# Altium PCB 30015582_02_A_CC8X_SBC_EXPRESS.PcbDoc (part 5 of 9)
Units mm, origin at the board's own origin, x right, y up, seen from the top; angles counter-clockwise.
Board outline 87 x 63 mm, 6 copper layers (Top Layer-L1, GND Plane-L2, Signal-L3, PWR/Signal-L4, GND Plane-L5, Bottom Layer-L6), stack 1.172 mm thick; 169 components, 171 nets, 693 pads, 391 vias.
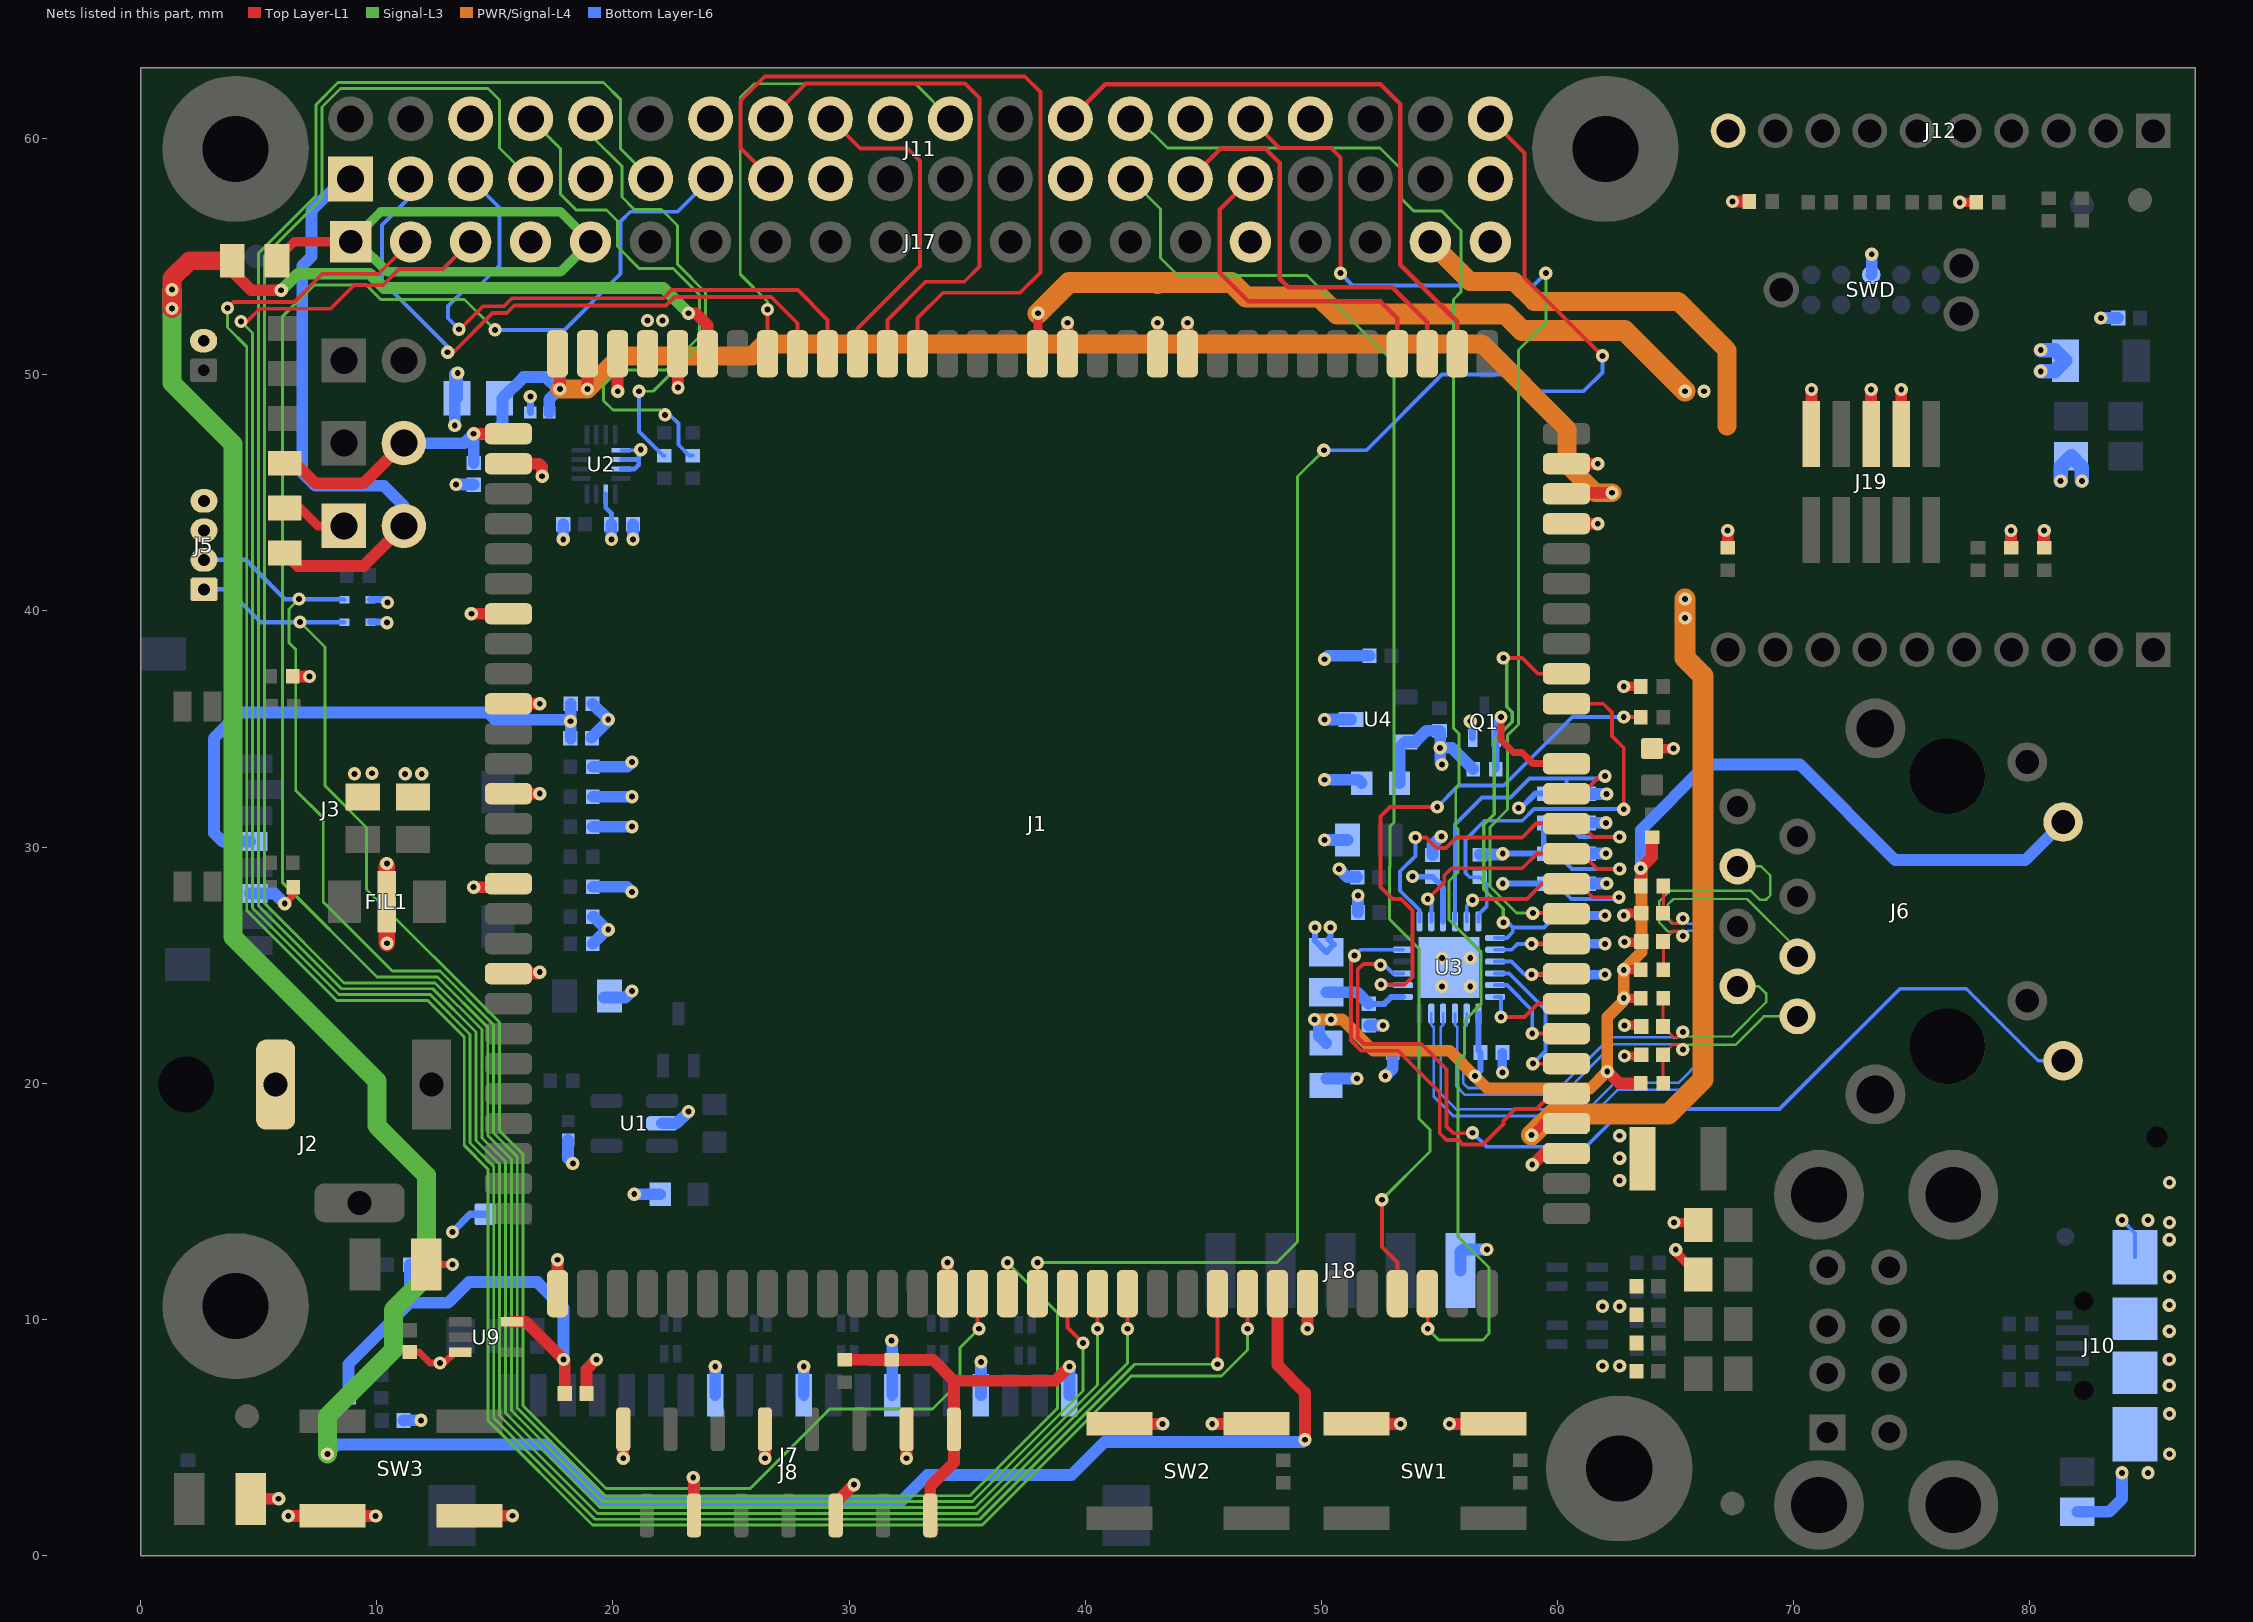
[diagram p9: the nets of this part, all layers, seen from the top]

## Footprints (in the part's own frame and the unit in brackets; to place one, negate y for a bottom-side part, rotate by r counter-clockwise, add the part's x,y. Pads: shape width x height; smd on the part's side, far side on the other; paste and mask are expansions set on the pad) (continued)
CC8X_CASTELLATED [mm] (continued)
  Top Layer-L1 keep-out region: 9.09,20.32 9.075,20.397 9.031,20.461 8.967,20.505 8.89,20.52 8.89,20.52 8.813,20.505 8.749,20.461 8.705,20.397 8.69,20.32 8.69,20.32 8.705,20.243 8.749,20.179 8.813,20.135 8.89,20.12 8.89,20.12 8.967,20.135 9.031,20.179 9.075,20.243 9.09,20.32
  Top Layer-L1 keep-out region: 10.36,20.32 10.345,20.397 10.301,20.461 10.237,20.505 10.16,20.52 10.16,20.52 10.083,20.505 10.019,20.461 9.975,20.397 9.96,20.32 9.96,20.32 9.975,20.243 10.019,20.179 10.083,20.135 10.16,20.12 10.16,20.12 10.237,20.135 10.301,20.179 10.345,20.243 10.36,20.32
  Top Layer-L1 keep-out region: 11.63,20.32 11.615,20.397 11.571,20.461 11.507,20.505 11.43,20.52 11.43,20.52 11.353,20.505 11.289,20.461 11.245,20.397 11.23,20.32 11.23,20.32 11.245,20.243 11.289,20.179 11.353,20.135 11.43,20.12 11.43,20.12 11.507,20.135 11.571,20.179 11.615,20.243 11.63,20.32
  Top Layer-L1 keep-out region: 12.9,20.32 12.885,20.397 12.841,20.461 12.777,20.505 12.7,20.52 12.7,20.52 12.623,20.505 12.559,20.461 12.515,20.397 12.5,20.32 12.5,20.32 12.515,20.243 12.559,20.179 12.623,20.135 12.7,20.12 12.7,20.12 12.777,20.135 12.841,20.179 12.885,20.243 12.9,20.32
  Top Layer-L1 keep-out region: 14.17,20.32 14.155,20.397 14.111,20.461 14.047,20.505 13.97,20.52 13.97,20.52 13.893,20.505 13.829,20.461 13.785,20.397 13.77,20.32 13.77,20.32 13.785,20.243 13.829,20.179 13.893,20.135 13.97,20.12 13.97,20.12 14.047,20.135 14.111,20.179 14.155,20.243 14.17,20.32
  Keep-Out Layer board cut-out: 16.78,9.93 16.742,10.121 16.634,10.284 16.471,10.392 16.28,10.43 16.28,10.43 -16.28,10.43 -16.471,10.392 -16.634,10.284 -16.742,10.121 -16.78,9.93 -16.78,9.93 -16.78,-9.93 -16.742,-10.121 -16.634,-10.284 -16.471,-10.392 -16.28,-10.43 -16.28,-10.43 16.28,-10.43 16.471,-10.392 16.634,-10.284 16.742,-10.121 16.78,-9.93 16.78,-9.93
  silkscreen extent -21.18,-22.6 20.1,22.6, body extent -20,-22.5 20,22.5, height 4.07
conn_CSCD443CCS011B00G [mil] "Bobbintron : CSCD443CCS011B00G"
  rect 65x150 hole 40 slot 126 at 90 deg: 1(0,0)
  rrect50% 65x150 / inner rect 65x150 / far side rrect50% 65x150 hole 40 slot 126 at 90 deg: 2(-260,0)
  rrect50% 150x65 / inner rect 150x65 / far side rrect50% 150x65 hole 40 slot 126 at 0 deg: 3(-120,-197.01)
  round 0 hole 93 unplated: 4(-409,0)
  silkscreen extent -570,-177 20,177, body extent -571,-207 20,177, height 433
FCI_68002-102HLF [mil]
  rect 74x74 hole 45: 1(0,0)
  round 74 hole 45: 2(100,0)
  silkscreen extent -50,-48 150,48, body extent -51,-46 149,49, height 330
FCI_SFW15S-2STE1LF [mm] "CONN FFC FPC VERT 15POS 1MM SMD"
  rrect50% 0.6x1.85 smd: 1(-7,-1.825) 2(-6,1.825) 3(-5,-1.825) 4(-4,1.825) 5(-3,-1.825) 6(-2,1.825) 7(-1,-1.825) 8(0,1.825) 9(1,-1.825) 10(2,1.825) 11(3,-1.825) 12(4,1.825) 13(5,-1.825) 14(6,1.825) 15(7,-1.825)
  silkscreen extent -10.9,-2.02 10.9,2.62, body extent -10.7,-2.25 10.7,2.25, height 5.31
fiducial_40mil_round [mil]
  round 40 smd paste-40 mask+20: 1(0,0)
  Top Layer-L1 pour cut-out: -40,0 -36.96,15.31 -28.28,28.28 -15.31,36.96 0,40 0,40 15.31,36.96 28.28,28.28 36.96,15.31 40,0 40,0 36.96,-15.31 28.28,-28.28 15.31,-36.96 0,-40 0,-40 -15.31,-36.96 -28.28,-28.28 -36.96,-15.31 -40,0
FIL_DLP11S [mm]
  rect 0.75x0.35 smd: 1(-0.65,-0.275) 2(0.65,-0.275) 3(0.65,0.275) 4(-0.65,0.275)
  body extent -0.67,-0.55 0.68,0.55, height 0.92
FIL_DLW21H [mm]
  rect 0.9x0.4 smd: 1(-0.85,-0.4) 2(0.85,-0.4) 3(0.85,0.4) 4(-0.85,0.4)
  body extent -1.1,-0.7 1.1,0.7, height 1
FIL_ELKEA [mm]
  rect 1.4x1.8 smd: 1(-1.8,0) 3(1.8,0)
  rect 0.8x2.6 smd: 2(0,0)
  body extent -1.6,-0.9 1.6,0.9, height 2.2
HIROSE_A2-20PA-2.54DSA(71) [mm]
  rect 1.75x1.75 hole 1 mask+0.1: 1(-24.13,0)
  round 1.75 hole 1 mask+0.1: 2(-21.59,0) 3(-19.05,0) 4(-16.51,0) 5(-13.97,0) 6(-11.43,0) 7(-8.89,0) 8(-6.35,0) 9(-3.81,0) 10(-1.27,0) 11(1.27,0) 12(3.81,0) 13(6.35,0) 14(8.89,0) 15(11.43,0) 16(13.97,0) 17(16.51,0) 18(19.05,0) 19(21.59,0) 20(24.13,0)
  silkscreen extent -25.33,-2.6 25.32,1.35, body extent -25.25,-1.27 25.25,1.27, height 8.55
HIROSE_DF14A-20P-1.25H [mm]
  rect 0.7x1.8 smd: 1(11.875,-2.55) 2(10.625,-2.55) 3(9.375,-2.55) 4(8.125,-2.55) 5(6.875,-2.55) 6(5.625,-2.55) 7(4.375,-2.55) 8(3.125,-2.55) 9(1.875,-2.55) 10(0.625,-2.55) 11(-0.625,-2.55) 12(-1.875,-2.55) 13(-3.125,-2.55) 14(-4.375,-2.55) 15(-5.625,-2.55) 16(-6.875,-2.55) 17(-8.125,-2.55) 18(-9.375,-2.55) 19(-10.625,-2.55) 20(-11.875,-2.55)
  rect 2x2.6 smd: MT1(14.275,2.55) MT21(-14.275,2.55)
  silkscreen extent -15,-3.05 15,3.7, body extent -14.97,-3.02 14.98,3.68, height 2.49
INDC2013X110N [mm]
  rect 1.2x1.45 smd: 1(-0.85,0) 2(0.85,0)
  body extent -1.1,-0.72 1.1,0.72, height 1.1
KYCON_KMMX-ABSMT5 [mm]
  rect 0.4x0.7 smd mask+0.058: 1(-1.3,3)
  rect 0.4x1.4 smd: 2(-0.65,2.65) 3(0,2.65) 4(0.65,2.65)
  rect 0.4x0.65 smd mask+0.058: 5(1.3,3.025)
  rect 2.3x1.9 smd: 6(-3.75,0) 9(3.75,0)
  rect 1.8x1.9 smd: 7(-1.15,0) 8(1.15,0)
  round 0 hole 0.813 unplated: 10(-1.9,2.18) 11(1.9,2.18)
  Top Layer-L1 region: 1.1,2.7 1.1,1.95 1.275,1.95 1.275,2.18 1.278,2.235 1.28,2.258 1.282,2.278 1.285,2.29 1.288,2.305 1.29,2.315 1.292,2.328 1.3,2.355 1.308,2.378 1.315,2.4 1.32,2.412 1.335,2.448 1.34,2.458 1.342,2.462 1.345,2.468 1.358,2.49 1.372,2.515 1.388,2.538 1.4,2.555 1.418,2.578 1.435,2.598 1.482,2.645 1.5,2.66 1.5,2.7
  Top Layer-L1 region: -1.1,2.7 -1.1,1.95 -1.275,1.95 -1.275,2.18 -1.278,2.235 -1.28,2.258 -1.282,2.278 -1.285,2.29 -1.288,2.305 -1.29,2.315 -1.292,2.328 -1.3,2.355 -1.308,2.378 -1.315,2.4 -1.32,2.412 -1.335,2.448 -1.34,2.458 -1.342,2.462 -1.345,2.468 -1.358,2.49 -1.372,2.515 -1.388,2.538 -1.4,2.555 -1.418,2.578 -1.435,2.598 -1.482,2.645 -1.5,2.66 -1.5,2.7
  silkscreen extent -3.75,-2.15 3.75,2.85, body extent -4.4,-2.72 4.4,2.88, height 2.78
KYCON_KUSBX-AS2N [mm]
  rect 1.524x1.524 hole 0.9: A1(0,0)
  round 1.524 hole 0.9: A2(2.5,0) A3(4.5,0) A4(7,0) B1(0,-2.62) B2(2.5,-2.62) B3(4.5,-2.62) B4(7,-2.62)
  round 3.81 hole 2.362: SH1(-3.07,-5.33) SH2(-3.07,0.35) SH3(10.07,-5.33) SH4(10.07,0.35)
  silkscreen extent -3.75,-15.58 10.75,1.42, body extent -4.33,-16.08 11.33,1.42, height 16.1
LEDM3020X130N [mm]
  rect 1.3x2.2 smd: A(-1.3,0) K(1.3,0)
  silkscreen extent -0.45,-1.1 2.25,1.1, body extent -1.6,-1.1 1.6,1.1, height 1.5
MOLEX_53047-0210 [mm]
  rrect20% 1x1.15 hole 0.5: 1(0,0)
  oval 1x1.15 hole 0.5: 2(1.25,0)
  silkscreen extent -2.51,-1.3 2.9,2.2, body extent -1.52,-1.15 2.73,2.05, height 4.2
MOLEX_53047-0410 [mm]
  rrect20% 1x1.15 hole 0.5: 1(0,0)
  oval 1x1.15 hole 0.5: 2(1.25,0) 3(2.5,0) 4(3.75,0)
  silkscreen extent -2.63,-1.33 5.43,2.22, body extent -1.52,-1.15 5.23,2.05, height 4.2
MOLEX_500873-0806 [mm]
  rect 0.8x1.5 smd: 1(0,0) 2(1.1,-0.4) 3(2.2,0) 4(3.3,0.2) 5(4.4,0) 6(5.5,0.2) 7(6.6,0) 8(7.7,0)
  rect 1.8x1.4 smd: 9(1.2,-10.3) 10(6.9,-10.3)
  rect 1.4x1.9 smd: 11(8.5,2.85) 12(-4.65,3.85)
  Top Layer-L1 keep-out region: 8.6,1.75 9.2,1.75 9.2,-11 8.6,-11
  silkscreen extent -5.05,-10.7 8.95,4.5, body extent -5.05,-10.7 8.95,4.5, height 1.87
PCBNUMBER [mm]
QFN40P260X180X55-16N [mm] "Quad Flat No-Lead (QFN), 0.40 mm pitch; rect., 4 pin X 4 pin, 2.60 mm L X 1.80 mm W X 0.55 mm H body"
  rect 0.81x0.2 smd: 1(-0.85,0.6) 2(-0.85,0.2) 3(-0.85,-0.2) 4(-0.85,-0.6) 9(0.85,-0.6) 10(0.85,-0.2) 11(0.85,0.2) 12(0.85,0.6)
  rect 0.2x0.81 smd: 5(-0.6,-1.25) 6(-0.2,-1.25) 7(0.2,-1.25) 8(0.6,-1.25) 13(0.6,1.25) 14(0.2,1.25) 15(-0.2,1.25) 16(-0.6,1.25)
  body extent -0.95,-1.35 0.95,1.35, height 0.55
QFN50P400X400X100-25T260X260N [mm] "Quad Flat No-Lead (QFN with Tab), 0.50 mm pitch; square, 6 pin X 6 pin, 4.00 mm L X 4.00 mm W X 1.00 mm H body"
  rrect54% 0.84x0.26 smd mask+0.05: 1(-1.95,1.25) 2(-1.95,0.75) 3(-1.95,0.25) 4(-1.95,-0.25) 5(-1.95,-0.75) 6(-1.95,-1.25) 13(1.95,-1.25) 14(1.95,-0.75) 15(1.95,-0.25) 16(1.95,0.25) 17(1.95,0.75) 18(1.95,1.25)
  rrect54% 0.26x0.84 smd mask+0.05: 7(-1.25,-1.95) 8(-0.75,-1.95) 9(-0.25,-1.95) 10(0.25,-1.95) 11(0.75,-1.95) 12(1.25,-1.95) 19(1.25,1.95) 20(0.75,1.95) 21(0.25,1.95) 22(-0.25,1.95) 23(-0.75,1.95) 24(-1.25,1.95)
  rect 2.6x2.6 smd paste-2.6 mask+0: 25(0,0)
  silkscreen extent -2.95,1.13 -2.75,1.32, body extent -2.05,-2.05 2.05,2.05, height 1
RESC1005X40N [mm]
  rect 0.57x0.62 smd mask+0.05: 1(-0.48,0) 2(0.48,0)
  body extent -0.5,-0.25 0.5,0.25, height 0.4
RESC1609X55N [mm]
  rect 0.9x1 smd mask+0.05: 1(-0.8,0) 2(0.8,0)
  body extent -0.87,-0.48 0.87,0.48, height 0.55
RESC2013X70N [mm]
  rect 1.05x1.4 smd: 1(-0.95,0) 2(0.95,0)
  body extent -1.1,-0.67 1.1,0.68, height 0.7
RESC3225X60N [mm]
  rect 1.1x2.7 smd: 1(-1.5,0) 2(1.5,0)
  body extent -1.7,-1.35 1.7,1.35, height 0.6
SAMTEC_FTSH-105-01-F-DV [mil]
  rect 110x29 smd: 1(-80,100) 2(80,100) 3(-80,50) 4(80,50) 5(-80,0) 6(80,0) 7(-80,-50) 8(80,-50) 9(-80,-100) 10(80,-100)
  silkscreen extent -172,93 -158,107, body extent -115,-208 115,208, height 325
SAMTEC_SQT-110-01-F-S [mm]
  rect 1.47x1.47 hole 0.98 paste-1.47: 1(0,0)
  round 1.47 hole 0.98 paste-1.47: 2(2,0) 3(4,0) 4(6,0) 5(8,0) 6(10,0) 7(12,0) 8(14,0) 9(16,0) 10(18,0)
  silkscreen extent -1.28,-1.12 19.28,1.12, body extent -1.15,-1 19.15,1, height 6.47
SODFL1006X43AN12 [mm]
  rect 0.43x0.32 smd: 1(-0.55,0) 2(0.55,0)
  body extent -0.58,-0.33 0.58,0.33, height 0.4
SOT65P210X100-3AN [mm]
  rect 0.5x1 smd: 1(-0.65,-1.1) 2(0.65,-1.1) 3(0,1.1)
  body extent -1.2,-1.12 1.2,1.12, height 1
SOT65P210X110-5N [mm]
  rect 0.4x0.95 smd: 1(-0.65,-1.1) 2(0,-1.1) 3(0.65,-1.1) 4(0.65,1.1) 5(-0.65,1.1)
  silkscreen extent -1.4,-1.1 1.1,0.67, body extent -1,-1.1 1,1.1, height 0.93
SOT95P240X110_GSD-3N [mm]
  rect 0.65x1.05 smd: D(0,1.15) G(-0.95,-1.15) S(0.95,-1.15)
  body extent -1.46,-1.2 1.46,1.2, height 1.1
SOT95P280X145-5N [mm]
  rrect50% 1.36x0.6 smd: 1(-1.18,0.95) 2(-1.18,0) 3(-1.18,-0.95) 4(1.18,-0.95) 5(1.18,0.95)
  body extent -1.4,-1.45 1.4,1.45, height 1.45
SOTFL50P160X80_GSD-3N [mm]
  rect 0.4x0.77 smd: D(0,0.69) G(-0.5,-0.69) S(0.5,-0.69)
  body extent -0.85,-0.85 0.85,0.85, height 0.8
SULLINS_GBC05SBSN-M89 [mil]
  rect 50x125 smd: 1(-200,-195) 2(-100,-195) 3(0,-195) 4(100,-195) 5(200,-195)
  silkscreen extent -258,-201 255,55, body extent -251,-233 249,277, height 140
SW_KSC221J [mm]
  rect 1x2.8 smd: 1(2,2.9) 2(2,-2.9) 3(-2,2.9) 4(-2,-2.9)
  silkscreen extent -3.1,-3.1 3.1,3.1, body extent -3.1,-3.4 3.1,3.4, height 3.5
SW_TDA02 [mm]
  rect 1.27x0.76 smd: 1(-3.81,0.635) 2(-3.81,-0.635) 3(3.81,-0.635) 4(3.81,0.635)
  silkscreen extent -4.25,-1.99 3.29,1.99, body extent -3.12,-1.84 3.13,1.84, height 2.3
TC_TC2050-IDC-NL [mil]
  round 31 smd paste-50: 1(-100,-25) 2(-50,-25) 3(0,-25) 4(50,-25) 5(100,-25) 6(100,25) 7(50,25) 8(0,25) 9(-50,25) 10(-100,25)
  round 59 hole 39.37 unplated: MT1(-150,0) MT2(150,40) MT3(150,-40)
  silkscreen extent -243,-91 243,91
TP0762 [mil] "30mil SMT Round Testpoint"
  round 30 smd paste-100: 1(0,0)
Wurth_61304021121 [mm] "CONN HEADER VERT 40POS 2.54"
  rect 1.9x1.9 hole 1.15: 1(0,0)
  round 1.9 hole 1.15: 2(0,2.54) 3(2.54,0) 4(2.54,2.54) 5(5.08,0) 6(5.08,2.54) 7(7.62,0) 8(7.62,2.54) 9(10.16,0) 10(10.16,2.54) 11(12.7,0) 12(12.7,2.54) 13(15.24,0) 14(15.24,2.54) 15(17.78,0) 16(17.78,2.54) 17(20.32,0) 18(20.32,2.54) 19(22.86,0) 20(22.86,2.54) 21(25.4,0) 22(25.4,2.54) 23(27.94,0) 24(27.94,2.54) 25(30.48,0) 26(30.48,2.54) 27(33.02,0) 28(33.02,2.54) 29(35.56,0) 30(35.56,2.54) 31(38.1,0) 32(38.1,2.54) 33(40.64,0) 34(40.64,2.54) 35(43.18,0) 36(43.18,2.54) 37(45.72,0) 38(45.72,2.54) 39(48.26,0) 40(48.26,2.54)
  silkscreen extent -2.14,-1.8 49.53,3.81, body extent -1.27,-1.27 49.53,3.81, height 8.57
XMultiple_XMG-9799-8821 [mm]
  round 1.524 hole 0.9: 1(1.27,6.35) 2(2.54,8.89) 3(3.81,6.35) 4(5.08,8.89) 5(6.35,6.35) 6(7.62,8.89) 7(8.89,6.35) 8(10.16,8.89)
  round 1.676 hole 1: 9(-0.61,-4.9) 10(1.93,-3.38) 11(9.5,-4.9) 12(12.04,-3.38)
  round 3.2 hole 3.2 unplated: MNT1(0,0) MNT2(11.43,0)
  round 2.54 hole 1.6: SHLD1(-2.035,3.05) SHLD2(13.465,3.05)
  silkscreen extent -2.29,-10.79 13.72,10.38, body extent -2.58,-10.96 14.02,10.38, height 13.57

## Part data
C1 C2 C29: library part 1000501, "CAP CER 47UF 6.3V 20% X5R 0805", Manufacturer="Taiyo Yuden", Manufacturer_Part_Number=JMK212BJ476MG-T, Package_Type=0805, Temp_Coef=X5R, Tolerance=20%, Voltage=6.3V
C3 C30: library part 1000073, "CAP CER 1UF 6.3V 20% X5R 0402", Manufacturer=Murata, Manufacturer_Part_Number=GRM155R60J105ME19D, Package_Type=0402, Temp_Coef=X5R, Voltage=6.3V
C4: library part 1001303, "CAP CER 2.2UF 16V 10% X5R 0603", Manufacturer="TDK Corporation", Manufacturer_Part_Number=C1608X5R1C225K080AB, Package_Type=0603, Tolerance=10%, Voltage=16V
C5 C22 C24: library part 1001168, "CAP CER 10UF 10V 20% X5R 0402", Manufacturer=Samsung, Manufacturer_Part_Number=CL05A106MP5NUNC, Package_Type=0402, Temp_Coef=X5R, Tolerance=20%, Voltage=10V
C6 C7 C8 C9 C10 C11 C13 C14 C15 C16 C21 C23 C25 C27 C28 C31 C33: library part 1000006, "CAP 100nF 16V 10% X7R 0402", Manufacturer=Murata, Manufacturer_Part_Number=GRM155R71C104KA88D, Package_Type=0402, Tolerance=10
C12 C17: library part 1000500, "CAP CER 4.7UF 25V 10% X5R 0805", Manufacturer=Murata, Manufacturer_Part_Number=GRM21BR61E475KA12L, Package_Type=0805, Temp_Coef=X5R, Tolerance=10%, Voltage=25V
C18: library part 1001167, "CAP CER 1UF 10V 10% X5R 0402", Manufacturer=Murata, Manufacturer_Part_Number=GRM155R61A105KE15D, Package_Type=0402, Temp_Coef=X5R, Tolerance=10%, Voltage=10V
C19: library part 1001576, "CAP CER 470PF 50V 5% NP0 0402", Manufacturer=Murata, Manufacturer_Part_Number=GRM1555C1H471JA01J, Package_Type=0402, Tolerance="+/- 5%"
C20: library part 1001024, "CAP CER 0.022UF 100V X7R 0603", Manufacturer="TDK Corporation", Manufacturer_Part_Number=C1608X7R2A223M080AA, Package_Type=0603
C26: library part 1000566, "CAP CER 100UF 10V 20% X5R 1206", Manufacturer="TDK Corporation", Manufacturer_Part_Number=C3216X5R1A107M, Package_Type=1206, Temp_Coef=X5R, Tolerance=20%, Voltage=10V
C32: library part 1000067, "CAP CER 1000PF 50V 10% X7R 0402", Manufacturer=Murata, Manufacturer_Part_Number=GRM155R71H102KA01D, Package_Type=0402
D1: library part 1000794, "DIODE SCHOTTKY 30V 200MA SOT323", Manufacturer="Fairchild Semiconductor", Manufacturer Alt 1=none, Manufacturer Part Num=0082610201, Package_Type=SOT323, Part Number=SDS1920004
D2 D3: library part 1001637, "TVS DIODE 3.3VWM SOD923", Manufacturer="On Semiconductor", Package_Type=SMT
D4: library part 1001190, "LED RED 653NM 20MA 1208 SMD", Manufacturer=Dialight, Package_Type=SMT
D5: library part 1001189, "LED GREEN 573NM 1208 SMD", Manufacturer=Dialight, Package_Type=SMT
FIDUCIAL1 FIDUCIAL2 FIDUCIAL3 FIDUCIAL7 FIDUCIAL8 FIDUCIAL9: library part CAD0023, "40 Mil Round Fiducial", Package_Type=SMT
FIL1: library part 1001918, "DNF 2 MHZ -1000 MHZ SMD", Manufacturer="Panasonic - ECG", Manufacturer_Part_Number=ELKEA333FA, Package_Type=SMT
J1: library part 1002609, "CC8X castellated - 55001984-02", Manufacturer=DIGI, Manufacturer_Part_Number=55001984-02, Package_Type=SMT
J2: library part 1001105, "DC Power Jack", Manufacturer="Bobbintron Electrical Corp", Package_Type=TH
J3: library part 1001118, "CONN TRANSFLSH R/A PUSH-PUSH SMD", Manufacturer=Molex, Package_Type=SMT
J4: library part 1001136, "CONN HEADER 2POS 1.25MM VERT TIN", Manufacturer=Molex, Manufacturer_Part_Number=53047-0210, Package_Type=TH
J5: library part 1001137, "CONN HEADER 4POS 1.25MM VERT TIN", Manufacturer=Molex, Manufacturer_Part_Number=53047-0410, Package_Type=TH
J6: library part 1001971, "CONN, RJ45 100BASE-T R/A, -40/85C", Manufacturer=XMultiple, Manufacturer_Part_Number=XMG-9799-8821-100D-L1TO-H-HIM, Package_Type=TH
J7: library part 1001132, "CONN HEADER 20POS 1.25MM R/A SMD", Manufacturer=Hirose, Manufacturer_Part_Number=DF14A-20P-1.25H, Package_Type=SMT
J8: library part 1001866, "CONN FFC FPC VERT 15POS 1MM SMD", Manufacturer=FCI, Package_Type=SMT
J9: library part 1001121, "USB Stacked Dual A type", Manufacturer=KYCON, Package_Type=TH
J10: library part 1001117, "CONN RECEPT MICRO-USB TYPE AB R/A", Manufacturer=KYCON, Package_Type=SMT
J11: library part 1002007, "CONN HEADER VERT 40POS 2.54", Manufacturer="Wurth Electronics Inc", Package_Type=TH
J12 J13: library part 1001648, "CONN RECEPT 10POS 10X1 2MM PCB TH", Manufacturer=Samtec, Package_Type=TH
J14 J15 J16: library part 1001128, "CONN HEADER 2POS .100\" SGL GOLD", Manufacturer=Samtec, Manufacturer_Part_Number=TSW-102-07-G-S, Package_Type=TH
J17: library part 1002537, "HEADER 20POS 2.54MM", Manufacturer=Hirose, Package_Type=TH
J18: library part 1002541, "CONN HEADER 5POS .100 RT/A SMD", Manufacturer=Sullins, Package_Type=SMT
J19: library part 1000034, "CONN HEADER 10POS DUAL .05\" SMD", Manufacturer=Samtec, Package_Type=SMT
L1 L7 L8 L9 L12 L13 L14 L15 L16: library part 1001174, "FERRITE BEAD 220 OHM 2.0A 0805", Manufacturer="Wurth Electronics Inc", Manufacturer_Part_Number=742792022, Package_Type=0805
L2 L3 L4 L5 L6: library part 1001014, "CHOKE COIL COMMON MODE 150MA SMD", Manufacturer=Murata, Manufacturer_Part_Number=DLP11SN900HL2L, Package_Type=SMT
L10 L11: library part 1001173, "CHOKE COM MODE 120 OHM .37A", Manufacturer="Wurth Electronics Inc", Package_Type=SMT
PCB1: library part 3000137, "PCB CCWM6_SBC_v0.3"
Q1: library part 1000715, "MOSFET N-CH 60V 115MA SOT-523F", Manufacturer="Fairchild Semiconductor", Package_Type=SOT523F
R1 R2 R8 R20 R77: library part 1001557, "RES 0.0 OHM 1/8W JUMP 0805 SMD", Manufacturer=Yageo, Manufacturer_Part_Number=RC0805JR-070RL, Package_Type=0805, Power=125
R3 R9 R23 R39 R44 R45 R46 R47 R48 R49 R50 R51 R52 R53 R55 R56 R58 R62 R63 R64 R65 R66 R67 R69 R76: library part 1000076, "RES 0.0 OHM 1/10W 0402 SMD", Manufacturer="Panasonic - ECG", Manufacturer_Part_Number=ERJ-2GE0R00X, Package_Type=0402, Power=10
R4 R5 R15 R16 R17 R18 R43 R54 R57 R60 R70 R72: library part 1000537, "RES 10.0K OHM 1/10W 1% 0402 SMD", Manufacturer="Panasonic - ECG", Manufacturer_Part_Number=ERJ-2RKF1002X, Package_Type=0402, Power=100, Tolerance=1%
R6: library part 1001200, "RES 12.0K OHM 1/10W 1% 0603 SMD", Manufacturer=Yageo, Manufacturer_Part_Number=RC0603FR-0712KL, Package_Type=0603, Power=100, Tolerance=1
R7: library part 1000142, "RES 20K OHM 1/10W 5% 0603 SMD", Manufacturer="Panasonic - ECG", Manufacturer_Part_Number=ERJ-3GEYJ203V, Package_Type=0603, Power=100, Tolerance=5
R10 R13 R24 R25 R26 R27 R28 R29 R30 R31 R32 R33: library part 1000038, "RES 4.7K OHM 1/10W 5% 0402 SMD", Manufacturer="Panasonic - ECG", Manufacturer_Part_Number=ERJ-2GEJ472X, Package_Type=0402, Power=100, Tolerance=5
R11 R12 R73: library part 1000480, "RES 100K OHM 1/10W 1% 0402 SMD", Manufacturer="Panasonic - ECG", Manufacturer_Part_Number=ERJ-2RKF1003X, Package_Type=0402, Power=100, Tolerance=1%
R14: library part 1001149, "RES 22.1K OHM 1/16W 1% 0402 SMD", Manufacturer="Vishay Dale", Manufacturer_Part_Number=CRCW040222K1FKED, Package_Type=0402, Power=0.063, Tolerance=±100ppm/°C
R19: library part 1000467, "RES 100 OHM 1/10W 1% 0402 SMD", Manufacturer="Panasonic - ECG", Manufacturer_Part_Number=ERJ-2RKF1000X, Package_Type=0402, Tolerance=1%
R22: library part 1000079, "RES 1.00K OHM 1/10W 1% 0402 SMD", Manufacturer="Panasonic - ECG", Manufacturer_Part_Number=ERJ-2RKF1001X, Package_Type=0402, Power=10
R34 R35 R36 R37: library part 1000466, "RES 49.9 OHM 1/10W 1% 0402 SMD", Manufacturer="Panasonic - ECG", Manufacturer_Part_Number=ERJ-2RKF49R9X, Package_Type=0402, Power=100, Tolerance=1%
R38: library part 1000828, "RES 12.1K OHM 1/10W 1% 0402 SMD", Manufacturer="Panasonic - ECG", Manufacturer_Part_Number=ERJ-2RKF1212X, Package_Type=0402, Power=100, Tolerance=1%
R40 R41: library part 1000465, "RES 150 OHM 1/10W 1% 0402 SMD", Manufacturer="Panasonic - ECG", Manufacturer_Part_Number=ERJ-2RKF1500X, Package_Type=0402, Power=100, Tolerance=1%
R42: library part 1000229, "RES 0.0 OHM 1/2W 1210 SMD", Manufacturer="Vishay Dale", Manufacturer_Part_Number=CRCW12100000Z0EA, Package_Type=1210
R59 R61 R68: library part 1001158, "RES 120 OHM 1/16W 1% 0402 SMD", Manufacturer=Yageo, Manufacturer_Part_Number=RC0402FR-07120RL, Package_Type=0402, Tolerance=1%
R71: library part 1000208, "RES 0.0 OHM 1/10W 0603", Manufacturer="Panasonic - ECG", Manufacturer_Part_Number=ERJ-3GEY0R00V, Package_Type=0603, Voltage=75V
R74 R75: library part 1001156, "RES 2.20K OHM 1/16W 1% 0402 SMD", Manufacturer=Yageo, Manufacturer_Part_Number=RC0402FR-072K2L, Package_Type=0402, Tolerance=1%
S3: library part 1001500, "SWITCH DIP 2POS HALF PITCH 24V", Manufacturer="C&K Components", Package_Type=SMT
SW1 SW2 SW3: library part 1001124, "SWITCH TACTILE SPST-NO 0.05A 32V", Manufacturer=ITT, Package_Type=SMT
SWD: library part CAD0066, "CBL PLUG-OF-NAILS 10-PIN", Package_Type=SMT
TP3: library part CAD0011, "TEST POINT 30mil PAD SMT", Package_Type=TP
U1: library part 1001979, "IC REG LDO ADJ 0.15A SOT25", Manufacturer="Diodes, Inc.", Manufacturer_Part_Number=AP2202K-ADJTRG1, Package_Type=SOT23-5
U2: library part 1002531, "IC BUS TRANSCVR TRI-ST DL 10UQFN", Manufacturer="Texas Instruments", Manufacturer_Part_Number=SN74AVC2T245RSWR, Package_Type=QFN
U3: library part 1001970, "TXRX ETHERNET 10/100 24VQFN", Manufacturer=Micrel, Manufacturer_Part_Number=LAN8720Ai-CP-TR, Package_Type=SMT
U4: library part 1001163, "MOSFET P-CH 20V 3.7A SOT23-3", Manufacturer="Vishay Siliconix", Package_Type=SMT
U9: library part 1000759, "TRANSLATOR 1BIT UNIDIRECT SC70-", Manufacturer="Fairchild Semiconductor", Package_Type=SC70

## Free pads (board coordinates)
  round 0.6 hole 0.9 unplated: 0(85.375,17.725)
  round 6.2 hole 2.8: TOOL1(4.02,59.563) TOOL2(62.02,59.563) TOOL3(4.02,10.563) TOOL4(62.611,3.683)

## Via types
v1: diameter 0.56, hole 0.25, Top Layer-L1 to Bottom Layer-L6, 391 vias

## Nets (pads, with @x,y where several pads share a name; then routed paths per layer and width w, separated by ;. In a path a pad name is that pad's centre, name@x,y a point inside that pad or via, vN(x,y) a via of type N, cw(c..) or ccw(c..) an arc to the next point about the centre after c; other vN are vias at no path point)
1V8: J1.27 J1.84 R77.2 | length 133.3
  Top Layer-L1 w0.5: R77.2@3.875,54.825 3.875,54.375 4.675,53.575 v1(5.95,53.575) ; v1(23.2,52.6) 23.5,52.6 24.003,52.097 J1.27@24.003,50.888 ; J1.84@48.133,11.088 48.133,8.067 49.3,6.9 v1(49.3,4.9)
  Top Layer-L1 w0.8: v1(1.325,52.8) v1(1.325,53.6) 1.325,54.075 2.075,54.825 R77.2@3.875,54.825
  Signal-L3 w0.5: v1(5.95,53.575) 6.65,54.275 9.7,54.275 10.3,53.675 22.125,53.675 v1(23.2,52.6)
  Signal-L3 w0.8: v1(1.325,53.6) v1(1.325,52.8) 1.325,49.65 3.902,47.073 3.902,26.198 10,20.1 10,18.2 12.1,16.1 12.1,11.8 10.7,10.4 10.7,8.7 7.904,5.904 v1(7.904,4.296)
  Bottom Layer-L6 w0.5: v1(7.904,4.296) 8.308,4.7 17.2,4.7 19.6,2.3 32.2,2.3 33.307,3.407 39.414,3.407 40.814,4.807 49.207,4.807 v1(49.3,4.9)
1V8_EXT: J17.1 J17.5 R77.1 | length 26.3
  Top Layer-L1 w0.4: R77.1@5.8,54.425 5.8,54.925 6.501,55.626 J17.1@8.89,55.626
  Signal-L3 w0.4: J17.1@8.89,55.626 9.174,55.626 10.449,54.351 17.775,54.351 J17.5@19.05,55.626 17.775,56.901 10.165,56.901 J17.1@8.89,55.626
3V3: J1.12 J1.16 J1.29 J1.95 J14.1 R1.2 | length 67
  Top Layer-L1 w0.381: R1.2@6.1,44.35 6.75,44.35 7.5,43.6 J14.1@8.6,43.6 J14.1@9.3,43.6 ; J1.16@37.973,50.888 38,50.915 v1(38,52.6) ; J1.12@43.053,50.888 v1(43.053,52.2) ; v1(58.9,17.8) 59.388,18.288 J1.95@60.373,18.288
  PWR/Signal-L4 w0.889: v1(38,52.6) 39.3,53.9 43.1,53.9 ; 43.053,53.853 43.1,53.9 ; v1(58.9,17.8) 59.8,18.7 64.7,18.7 66.151,20.151 66.151,37.249 65.4,38 v1(65.4,39.7) v1(65.4,40.5) ; v1(65.4,49.3) 62.825,51.875 58.5,51.875 57.8,52.575 50.65,52.575 49.925,53.3 46.8,53.3 46.2,53.9 43.1,53.9
  other v1: 66.2,49.3 21.463,52.3 22.1,52.3
3V3_ETH0: C9.1 C32.2 L1.1 R22.1 R23.2 R24.2 R25.2 R26.1 R27.1 R28.1 R29.1 R71.2 U3.9 U4.D | length 20.7
  Bottom Layer-L6 w0.25: v1(49.725,26.6) 49.725,26.025 L1.1@50.2,25.55 50.525,25.875 50.3,26.1 50.375,26.175 v1(50.375,26.6) ; v1(53.85,28.75) 53.86,28.74 C9.1@54.7,28.74 55.15,28.29 U3.9@55.15,26.85 ; v1(57.675,28.448) R27.1@59.413,28.448 ; v1(57.675,29.718) R28.1@59.413,29.718 R29.1@59.413,31.018 ; v1(58.35,31.65) 58.45,31.65 59.058,32.258 R26.1@59.413,32.258
  Bottom Layer-L6 w0.4: R24.2@60.88,24.6 v1(62,24.6) ; R25.2@60.88,25.9 v1(62,25.9) ; R23.2@60.88,27.1 v1(62,27.1)
  Bottom Layer-L6 w0.5: v1(50.125,32.85) 51.55,32.85 R71.2@51.7,32.7 ; v1(50.125,35.4) U4.D@51.25,35.4 ; v1(50.125,37.95) 50.275,38.1 C32.2@52.04,38.1 ; R22.1@56.7,29.68 57.637,29.68 v1(57.675,29.718)
3V3_EXT: C5.2 C6.2 C8.2 C21.2 J3.4 J5.3 J7.1 J8.1 J8.2 J11.1 J11.17 J14.2 J17.19 L15.1 R1.1 R14.2 R15.2 R16.2 R17.2 R18.2 R60.2 R68.1 R70.2 R71.1 R72.2 R73.2 R74.2 R75.2 U2.6 U4.S U9.5 | length 124.2
  Top Layer-L1 w0.5: R1.1@6.1,42.45 6.65,41.9 9.44,41.9 J14.2@11.14,43.6 ; U9.5@15.725,9.9 16.3,9.9 v1(17.9,8.3) 17.955,8.245 C21.2@17.955,6.858 ; R74.2@29.807,8.287 30.893,8.287 30.9,8.28 R75.2@31.8,8.28 33.551,8.28 34.433,7.397 ; J8.2@33.533,1.1 33.433,1 J8.2@33.433,1.694 33.433,2.933 34.433,3.933 J8.1@34.433,5.344 34.433,7.397 ; v1(39.328,8) 38.726,7.397 34.433,7.397
  PWR/Signal-L4 w0.8: J17.19@54.61,55.626 56.286,53.95 58.15,53.95 59,53.1 65.1,53.1 67.175,51.025 67.175,47.825
  Bottom Layer-L6 w0.2: U2.6@19.696,44.955 19.696,44.365 19.933,44.128 19.933,43.673 C8.2@19.925,43.665
  Bottom Layer-L6 w0.5: J3.4@4.626,30.228 3.472,30.228 3.1,30.6 3.1,34.6 4.2,35.7 14.7,35.7 15.009,35.391 v1@18.209,35.391 ; R60.2@8.8,6.68 8.8,8.1 11.4,10.7 ; J11.1@8.89,58.293 8.593,58.293 7.232,56.932 7.232,55.003 6.843,54.614 6.843,45.857 7.4,45.3 10.3,45.3 11.14,44.46 J14.2@11.14,43.6 ; R68.1@11.402,12.319 11.402,10.702 13.027,10.702 13.9,11.575 16.8,11.575 17.9,10.475 v1(17.9,8.3) ; v1(18.2,35.325) 18.2,35.382 v1@18.209,35.391 ; C5.2@18.209,34.6 v1@18.209,35.391 ; C6.2@18.209,36.068 v1@18.209,35.391 ; R70.2@19.149,25.908 19.741,26.5 19.19,27.051 R17.2@19.149,27.051 ; R18.2@19.149,28.321 20.579,28.321 v1(20.8,28.1) ; R14.2@19.149,30.861 v1(20.8,30.861) ; R15.2@19.149,32.131 v1(20.8,32.131) ; R16.2@19.149,33.401 20.601,33.401 v1(20.8,33.6) ; C8.2@19.925,43.665 19.925,43.036 v1(19.933,43.028) ; J7.1@39.328,6.794 v1(39.328,8) ; R71.1@53.3,32.7 53.3,34.2 U4.S@53.55,34.45 53.975,34.45 54.445,34.92 R72.2@55,34.92 55.025,34.895 v1(55.025,34.2) ; v1(55.1,33.5) 55.025,33.575 v1(55.025,34.2) ; R73.2@56.42,33.3 55.52,34.2 v1(55.025,34.2)
  Bottom Layer-L6 w0.61: v1(81.3,45.5) 81.3,46.1 L15.1@81.742,46.542 82.2,46.084 v1(82.2,45.5)
  other v1: 19.8,26.5
5V_CC8X: C29.2 C30.2 C31.1 J1.31 J1.32 J1.33 J1.116 J15.2 R2.2 | length 73.6
  Top Layer-L1 w0.5: R2.2@6.1,46.25 6.55,46.25 7.4,45.4 9.44,45.4 J15.2@11.14,47.1 ; v1(14.1,47.5) 15.571,47.5 J1.33@15.573,47.498 ; J1.32@17.653,50.888 17.75,50.791 v1(17.75,49.4) ; v1(18.923,49.4) J1.31@18.923,50.888 ; J1.116@60.373,44.958 60.415,45 v1(62.3,45)
  PWR/Signal-L4 w0.8: v1(17.75,49.4) v1(18.923,49.4) 20.323,50.8 25.9,50.8 26.4,51.3 56.8,51.3 60.4,47.7 60.4,46.2 61.6,45 v1(62.3,45)
  Bottom Layer-L6 w0.5: J15.2@11.14,47.1 13.7,47.1 v1(14.1,47.5) ; C31.1@14.1,46.26 v1(14.1,47.5) ; C30.2@17.3,48.4 17.3,48.95 v1(17.75,49.4) ; v1(18.923,49.4) v1(17.75,49.4) ; v1(14.1,47.5) 14.9,47.5 15.315,47.915 15.315,49 16.215,49.9 17.153,49.9 17.653,49.4 v1(17.75,49.4)
ADC_IN0: J1.83 J17.2 | length 102.3
  Top Layer-L1 w0.165: v1(3.675,52.825) 3.935,53.085 6.51,53.085 7.7,54.275 10.079,54.275 J17.2@11.43,55.626 ; v1(46.863,9.6) J1.83@46.863,11.088
  Signal-L3 w0.122: v1(3.675,52.825) 3.675,52 4.49,51.185 4.49,27.31 8.3,23.5 12.158,23.5 13.7,21.958 13.7,17.37 14.7,16.37 14.7,5.726 19.139,1.287 35.632,1.287 41.945,7.6 45.762,7.6 46.863,8.701 v1(46.863,9.6)
ADC_IN1: J1.82 J17.3 | length 102.4
  Top Layer-L1 w0.165: v1(4.25,52.25) 4.5,52.25 5.043,52.793 8.043,52.793 9.04,53.79 10.263,53.79 10.942,54.468 12.793,54.468 13.951,55.626 J17.3@13.97,55.626 ; J1.82@45.593,11.088 45.593,9.015 45.6,9.008 v1(45.6,8.1)
  Signal-L3 w0.122: v1(4.25,52.25) 4.739,51.761 4.739,27.413 8.403,23.749 12.261,23.749 13.949,22.061 13.949,17.473 14.949,16.473 14.949,5.829 19.242,1.536 35.529,1.536 42.093,8.1 v1(45.6,8.1)
AVDD1: C10.2 C11.1 C12.2 J6.11 L1.2 R34.2 R35.2 R36.2 R37.2 R39.1 U3.1 U3.19 | length 59
  Top Layer-L1 w0.4: v1(62.8,23.6) R35.2@63.52,23.6 ; v1(62.8,24.8) R37.2@63.52,24.8
  Top Layer-L1 w0.5: v1(62.1,20.5) 62.6,20 R34.2@63.52,20 ; R36.2@63.52,28.35 v1(63.52,29.1) 64,29.58 R39.1@64,30.42
  PWR/Signal-L4 w0.5: v1(49.7,22.7) v1(50.4,22.7) 50.875,22.7 52.2,21.375 55.425,21.375 v1(56.5,20.3) 57.025,19.775 61.375,19.775 v1(62.1,20.5) 62.1,22.8 62.8,23.5 v1(62.8,23.6) v1(62.8,24.8) 63.557,25.557 63.557,29.063 v1(63.52,29.1)
  Bottom Layer-L6 w0.25: C11.1@52,23.36 52.66,23.36 52.95,23.65 U3.1@53.45,23.65 ; v1(56.5,20.3) 56.74,20.54 C10.2@56.74,21.3 56.65,21.39 U3.19@56.65,22.95
  Bottom Layer-L6 w0.5: v1(49.7,22.7) 49.9,22.5 49.9,22 C12.2@50.2,21.7 ; L1.2@50.2,23.85 51.51,23.85 C11.1@52,23.36 ; v1(63.52,29.1) 63.52,30.72 66.3,33.5 70.25,33.5 74.3,29.45 79.794,29.45 J6.11@81.403,31.058
CONSOLE_RX: D2.2 J1.75 J5.2 | length 80.6
  Top Layer-L1 w0.165: v1(36.7,12.4) 36.703,12.397 J1.75@36.703,11.088
  Signal-L3 w0.121: 6.282,38.65 6.282,40.082 v1(6.7,40.5)
  Signal-L3 w0.122: 6.282,38.65 6.568,38.364 6.568,32.4 7.732,31.236 7.732,27.668 10.655,24.745 12.673,24.745 14.945,22.473 14.945,17.886 15.945,16.886 15.945,6.242 19.654,2.532 35.118,2.532 38.818,6.232 38.818,10.282 v1(36.7,12.4)
  Bottom Layer-L6 w0.191: J5.2@2.68,42.158 4.442,42.158 6.1,40.5 v1(6.7,40.5) 8.6,40.5 D2.2@8.625,40.475
CONSOLE_TX: D3.2 J1.74 J5.1 | length 69.5
  Top Layer-L1 w0.165: J1.74@35.433,11.088 35.433,9.667 v1(35.5,9.6)
  Signal-L3 w0.122: v1(6.75,39.525) 7.8,38.475 7.8,32.596 9.568,30.828 9.568,28.202 15.194,22.576 15.194,17.989 16.194,16.989 16.194,6.345 19.706,2.832 25.809,2.832 29.177,6.2 33.528,6.2 34.7,7.372 34.7,8.8 v1(35.5,9.6)
  Bottom Layer-L6 w0.191: J5.1@2.68,40.908 3.692,40.908 5.075,39.525 v1(6.75,39.525) D3.2@8.625,39.525
ENET0_CLK: J1.96 U3.5 | length 18.7
  Top Layer-L1 w0.165: v1(51.4,25.4) 51.241,25.241 51.241,21.807 51.674,21.375 53.245,21.375 55.008,19.612 55.008,17.879 55.301,17.586 55.8,17.586 55.976,17.41 56.836,17.41 57.7,18.274 57.7,18.4 58.2,18.9 59.1,18.9 59.758,19.558 J1.96@60.373,19.558
  Bottom Layer-L6 w0.165: v1(51.4,25.4) 51.65,25.65 U3.5@53.45,25.65
ENET0_INT#: J1.101 R25.1 U3.14 | length 4.1
  Top Layer-L1 w0.165: v1(58.9,25.9) 58.908,25.908 J1.101@60.373,25.908
  Bottom Layer-L6 w0.165: U3.14@57.35,25.65 58.05,25.65 58.3,25.9 v1(58.9,25.9) R25.1@59.92,25.9
ENET0_MDC: J1.110 R23.1 U3.13 | length 19
  Top Layer-L1 w0.165: v1(57.7,38) 58.5,38 59.162,37.338 J1.110@60.373,37.338
  Signal-L3 w0.15: v1(57.7,26.8) 57.7,27.391 56.874,28.217 56.874,30.945 57.323,31.394 57.323,34.541 58.082,35.3 58.082,35.7 57.839,35.943 57.839,37.861 v1(57.7,38)
  Bottom Layer-L6 w0.165: U3.13@57.35,26.15 57.85,26.15 58.1,26.4 58.1,26.6 ; R23.1@59.92,27.1 59.42,26.6 58.1,26.6 ; 57.982,26.718 57.782,26.718 v1(57.7,26.8) 57.9,26.8 57.982,26.718 ; 57.982,26.718 58.1,26.6
ENET0_MDIO: J1.109 R22.2 U3.12 | length 17.8
  Top Layer-L1 w0.165: J1.109@60.373,36.068 61.932,36.068 62.3,35.7 62.3,34.7 62.8,34.2 v1(62.8,31.6)
  Bottom Layer-L6 w0.165: U3.12@56.65,26.85 56.65,27.15 57,27.5 57,28.42 R22.2@56.7,28.72 56.28,28.72 56.1,28.9 56.1,30.3 56.91,31.11 58.503,31.11 59.003,31.611 62.789,31.611 v1(62.8,31.6)
ENET0_PWR: J1.107 Q1.G R73.1 | length 6.4
  Top Layer-L1 w0.3: v1(57.6,35.5) 57.6,34.539 58.134,34.005 58.491,34.005 58.968,33.528 J1.107@60.373,33.528
  Bottom Layer-L6 w0.3: R73.1@57.38,33.3 57.38,34.59 Q1.G@57.4,34.61 57.4,35.3 v1(57.6,35.5)
ENET0_RESET: J1.100 R24.1 U3.15 | length 4.3
  Top Layer-L1 w0.165: v1(58.9,24.6) 60.335,24.6 J1.100@60.373,24.638
  Bottom Layer-L6 w0.165: U3.15@57.35,25.15 58.05,25.15 58.6,24.6 v1(58.9,24.6) R24.1@59.92,24.6
ENET0_RX_CTL: J1.103 R27.2 R31.1 U3.11 | length 10.2
  Top Layer-L1 w0.165: 56.7,27.8 58.7,27.8 59.348,28.448 J1.103@60.373,28.448 60.902,28.448 61.475,27.875 v1(62.6,27.875)
  Bottom Layer-L6 w0.165: U3.11@56.15,26.85 56.15,27.5 v1(56.4,27.75) ; R31.1@60.373,28.448 60.373,28.002 60.575,27.8 62.525,27.8 v1(62.6,27.875)
ENET0_RX_ER: J1.106 R26.2 R30.1 U3.10 | length 14.8
  Top Layer-L1 w0.165: J1.106@59.442,32.258 J1.106@60.373,32.258 61.058,32.258 61.8,33 v1(62,33)
  Bottom Layer-L6 w0.165: U3.10@55.65,26.85 55.65,30.95 56.8,32.1 58,32.1 58.8,32.9 60.373,32.9 ; R30.1@60.373,32.258 60.373,32.9 ; v1(62,33) 61.9,32.9 60.373,32.9
ENET0_RXD0: J1.104 R28.2 R32.1 U3.8 | length 13.1
  Top Layer-L1 w0.165: v1(54.5,27.8) 55.2,28.5 55.2,28.8 55.5,29.1 58.5,29.1 59.118,29.718 J1.104@60.373,29.718 61.032,29.718 61.675,29.075 v1(62.625,29.075)
  Bottom Layer-L6 w0.165: v1(54.5,27.8) 54.65,27.65 U3.8@54.65,26.85 ; R32.1@60.373,29.718 60.373,29.302 60.6,29.075 v1(62.625,29.075)
ENET0_RXD1: J1.105 R29.2 R33.1 U3.7 | length 16.2
  Top Layer-L1 w0.165: v1(53.975,30.4) 54.433,30.4 54.872,29.96 55.278,29.96 55.717,30.4 58.5,30.4 59.088,30.988 J1.105@60.373,30.988 60.937,30.988 61.5,30.425 v1(62.625,30.425)
  Bottom Layer-L6 w0.165: v1(53.975,30.4) 53.975,29.625 53.325,28.975 53.325,28.15 54.15,27.325 U3.7@54.15,26.85 ; R33.1@60.373,31.018 60.373,30.983 60.931,30.425 v1(62.625,30.425)
ENET0_TX_CTL: J1.97 U3.16 | length 6.7
  Top Layer-L1 w0.165: v1(58.95,20.825) 60.37,20.825 J1.97@60.373,20.828
  Bottom Layer-L6 w0.165: U3.16@57.35,24.65 57.95,24.65 59.49,23.11 59.49,21.365 v1(58.95,20.825)
ENET0_TXD0: J1.98 U3.17 | length 4.4
  Top Layer-L1 w0.165: v1(58.925,22.1) 60.371,22.1 J1.98@60.373,22.098
  Bottom Layer-L6 w0.165: U3.17@57.35,24.15 57.85,24.15 58.925,23.075 v1(58.925,22.1)
ENET0_TXD1: J1.99 U3.18 | length 4.1
  Top Layer-L1 w0.165: v1(57.6,22.8) 58.6,22.8 59.168,23.368 J1.99@60.373,23.368
  Bottom Layer-L6 w0.165: U3.18@57.35,23.65 57.6,23.65 v1(57.6,22.8)
ETH0_LED1/#REGOFF: J6.9 U3.3 | length 42.3
  Top Layer-L1 w0.165: v1(52.5,25) 52.452,25.048 51.773,25.048 51.533,24.808 51.533,21.928 51.795,21.667 54.223,21.667 55.3,20.59 55.3,18.162 55.583,17.878 56.378,17.878 v1(56.4,17.9)
  Bottom Layer-L6 w0.165: v1(52.5,25) 52.675,25 53.025,24.65 U3.3@53.45,24.65 ; v1(56.4,17.9) 56.99,17.31 61.21,17.31 62.8,18.9 69.4,18.9 74.5,24 77.3,24 80.352,20.948 J6.9@81.403,20.948
ETH0_LED2/#NINTSEL: R41.1 U3.2 | length 22.7
  Top Layer-L1 w0.165: v1(52.525,24.175) 53.524,24.175 53.849,24.5 53.849,27.319 53.368,27.8 53,27.8 52.5,28.3 52.5,31.3 52.9,31.7 v1(54.9,31.7) ; v1(62.8,35.5) 63.48,35.5 63.5,35.48 R41.1@63.52,35.5
  Bottom Layer-L6 w0.165: v1(52.525,24.175) 52.55,24.15 U3.2@53.45,24.15 ; v1(54.9,31.7) 55.8,32.6 57.719,32.6 60.619,35.5 v1(62.8,35.5)
ETH0_RX_N: C16.1 J6.6 R37.1 U3.22 | length 33.7
  Top Layer-L1 w0.114: C16.1@64.46,26 64.46,26.014 64.9,26.454 65.1,26.454 65.3,26.254 v1(65.3,26.232) ; R37.1@64.48,24.8 C16.1@64.48,25.98
  Signal-L3 w0.102: v1(65.3,26.232) 65.109,26.422 64.678,26.422 64.3,26.8 64.3,27.7 64.756,28.156 68.172,28.156 68.553,27.775 68.825,27.775 69,27.95 69,28.8 68.622,29.178 J6.6@67.613,29.178
  Bottom Layer-L6 w0.114: U3.22@55.15,22.95 55.15,22.473 55.046,22.369 55.046,19.554 55.7,18.9 61.3,18.9 62.412,20.012 65.113,20.012 66.1,21 66.1,26.1 65.746,26.454 65.522,26.454 v1(65.3,26.232)
ETH0_RX_P: C15.1 J6.3 R36.1 U3.23 | length 33.7
  Top Layer-L1 w0.114: C15.1@64.46,27.2 64.9,26.76 64.9,26.746 65.1,26.746 65.3,26.946 v1(65.3,26.969) ; C15.1@64.48,27.22 R36.1@64.48,28.35
  Signal-L3 w0.102: v1(65.3,26.969) 65.109,26.778 64.825,26.778 64.656,26.947 64.656,27.553 64.903,27.8 68.025,27.8 70.153,25.672 J6.3@70.153,25.368
  Bottom Layer-L6 w0.114: U3.23@54.65,22.95 54.65,22.473 54.754,22.369 54.754,19.433 55.579,18.608 61.421,18.608 62.533,19.72 65.233,19.72 66.392,20.879 66.392,26.221 65.867,26.746 65.522,26.746 v1(65.3,26.969)
ETH0_TX_N: C14.1 J6.2 R35.1 U3.20 | length 21.6
  Top Layer-L1 w0.114: R35.1@64.48,23.6 64.46,23.58 C14.1@64.46,22.4 64.517,22.343 64.517,22.329 64.9,21.946 65.1,21.946 65.3,22.146 v1(65.3,22.169)
  Signal-L3 w0.102: v1(65.3,22.169) 65.491,21.978 67.378,21.978 68.825,23.425 68.825,23.8 68.527,24.098 J6.2@67.613,24.098
  Bottom Layer-L6 w0.114: U3.20@56.15,22.95 56.15,22.473 56.046,22.369 56.046,20.779 56,20.733 56,20 56.2,19.8 60.087,19.8 62.233,21.946 65.078,21.946 v1(65.3,22.169)
ETH0_TX_P: C13.1 J6.1 R34.1 U3.21 | length 21.6
  Top Layer-L1 w0.114: R34.1@64.48,20 64.46,20.02 C13.1@64.46,21.2 64.517,21.257 64.517,21.271 64.9,21.654 65.1,21.654 65.3,21.454 v1(65.3,21.432)
  Signal-L3 w0.102: v1(65.3,21.432) 65.491,21.622 67.525,21.622 68.731,22.828 J6.1@70.153,22.828
  Bottom Layer-L6 w0.114: U3.21@55.65,22.95 55.65,22.473 55.754,22.369 55.754,20.9 55.708,20.854 55.708,19.879 56.079,19.508 60.208,19.508 62.354,21.654 65.078,21.654 v1(65.3,21.432)
EXPANSION_UART_RX: J11.10 R65.1 R67.1 | length 18.9
  Signal-L3 w0.122: J11.10@19.05,60.833 19.05,60.155 20.379,58.826 20.379,57.521 20.9,57 22.05,57 22.726,56.324 22.726,54.676 23.917,53.485 23.917,51.515 21.702,49.3 v1(21.1,49.3)
  Bottom Layer-L6 w0.165: v1(21.1,49.3) 21.1,47.592 22.117,46.575 R65.1@22.175,46.575
EXPANSION_UART_TX: J11.8 R64.1 R66.1 | length 24.6
  Signal-L3 w0.122: J11.8@16.51,60.833 17.77,59.573 17.77,57.65 18.445,56.975 19.725,56.975 20.186,56.514 20.186,55.424 21.119,54.49 22.56,54.49 23.668,53.382 23.668,51.618 22.25,50.2 20.25,50.2 19.6,49.55 19.6,48.9 20,48.5 22,48.5 v1(22.2,48.3)
  Bottom Layer-L6 w0.165: v1(22.2,48.3) 22.405,48.3 22.768,47.937 22.768,47.032 23.225,46.575 R64.1@23.375,46.575
GND: C1.1 C2.1 C3.1 C4.1 C5.1 C6.1 C7.1 C8.1 C9.2 C10.1 C11.2 C12.1 C13.2 C14.2 C15.2 C16.2 C17.1 C18.1 C19.1 C20.1 C21.1 C22.1 C23.1 C24.1 C25.1 C26.2 C27.1 C28.1 C29.1 C30.1 C31.2 C33.1 D2.1 D3.1 D4.K D5.K FIL1.2 J1.11 J1.15 J1.28 J1.30 J1.34 J1.39 J1.42 J1.45 J1.48 J1.51 J1.60 J1.73 J1.85 J1.94 J1.115 J1.117 J2.2 J3.6 J4.2 J5.4 J7.4 J7.7 J7.10 J7.13 J8.3 J8.6 J8.9 J8.12 J8.15 J10.6 J10.7 J10.8 J10.9 J11.6 J11.9 J11.14 J11.20 J11.25 J11.30 J11.34 J11.39 J12.10 J17.4 J17.16 J17.20 J18.5 J19.3 J19.5 J19.9 L12.1 L13.1 L14.1 Q1.S R7.1 R11.1 R12.1 R20.1 R30.2 R31.2 R32.2 R33.2 R38.1 R40.2 R42.1 R50.1 R54.1 R55.2 R57.1 R58.2 SW1.1 SW1.2 SW2.1 SW2.2 SW3.1 SW3.2 SWD.3 U1.2 U2.1 U2.2 U2.3 U3.25 U9.3 | length 120.2
  Top Layer-L1 w0.3: v1(6.1,27.6) 6.455,27.955 R12.1@6.455,28.3 ; C33.1@11.4,8.615 11.785,8.615 12.25,8.15 v1(12.675,8.15) 12.85,8.15 U9.3@13.275,8.575 ; D5.K@12.095,12.319 v1(13.208,12.319)
  Top Layer-L1 w0.4: v1(62.8,27.1) 62.9,27.2 C15.2@63.54,27.2 ; v1(62.8,36.8) R40.2@63.52,36.8 ; v1(62.825,21.15) 63.49,21.15 C13.2@63.54,21.2 ; v1(62.825,22.45) 63.49,22.45 C14.2@63.54,22.4 ; v1(62.825,25.975) 63.515,25.975 C16.2@63.54,26 ; C20.1@64,34.17 v1(64.9,34.17) ; v1(64.925,14.1) 65.85,14.1 L13.1@65.95,14 ; v1(65,12.95) 65,12.85 L12.1@65.95,11.9 ; v1(77.025,57.3) R50.1@77.72,57.3
  Top Layer-L1 w0.5: D4.K@4.656,2.402 v1(5.842,2.402) ; v1(6.25,1.675) 8.111,1.675 SW3.2@8.119,1.683 8.127,1.675 v1(9.95,1.675) ; R11.1@6.449,37.225 v1(7.15,37.225) ; SW3.1@13.919,1.683 v1(15.748,1.683) ; v1(14,39.878) J1.39@15.573,39.878 ; v1(14.1,28.3) 15.425,28.3 J1.48@15.573,28.448 ; J1.51@15.573,24.638 16.838,24.638 v1(16.9,24.7) ; J1.45@15.573,32.258 v1(16.9,32.258) ; J1.42@15.573,36.068 v1(16.9,36.068) ; J1.34@15.573,46.228 16.872,46.228 17,46.1 v1(17,45.7) ; v1(17.65,12.525) 17.65,11.091 J1.60@17.653,11.088 ; C21.1@18.875,6.858 18.875,7.875 v1(19.3,8.3) ; J1.30@20.193,50.888 20.193,49.307 v1(20.2,49.3) ; v1(20.433,4.118) J8.15@20.433,5.344 ; J1.28@22.733,50.888 22.75,50.871 v1(22.75,49.45) ; v1(23.4,3.3) 23.433,3.267 J8.12@23.433,1.694 ; v1(26.433,4.118) J8.9@26.433,5.344 ; J8.6@29.433,1.694 29.433,2.233 v1(30.2,3) ; v1(32.433,4.118) J8.3@32.433,5.344 ; J1.73@34.163,11.088 v1(34.163,12.4) ; J1.15@39.243,50.888 v1(39.243,52.2) ; SW2.1@41.446,5.572 41.449,5.575 v1(43.275,5.575) ; J1.11@44.323,50.888 v1(44.323,52.2) ; v1(45.375,5.575) 47.244,5.575 SW2.2@47.246,5.572 ; v1(49.4,9.6) 49.403,9.603 J1.85@49.403,11.088 ; SW1.1@51.479,5.572 51.482,5.575 v1(53.35,5.575) ; v1(55.425,5.575) 57.277,5.575 SW1.2@57.279,5.572 ; v1(58.925,16.55) 58.95,16.55 59.418,17.018 J1.94@60.373,17.018 ; J1.115@60.373,43.688 v1(61.7,43.688) ; J1.117@60.373,46.228 v1(61.7,46.228) ; v1@61.875,10.575 v1(61.9,10.55) ; R58.2@67.2,42.68 v1(67.2,43.4) ; v1(67.4,57.331) R54.1@68.119,57.331 ; J19.9@70.739,47.498 70.75,47.509 v1(70.75,49.375) ; v1(73.275,49.375) 73.275,47.502 J19.5@73.279,47.498 ; J19.3@74.549,47.498 74.55,47.499 v1(74.55,49.375) ; R55.2@79.2,42.68 v1(79.2,43.4) ; R57.1@80.6,42.68 v1(80.6,43.4)
  Top Layer-L1 w0.7: v1@10.422,29.2 FIL1.2@10.422,27.69 10.425,27.687 v1(10.425,25.925)
  Bottom Layer-L6 w0.15: U2.1@20.346,46.805 21.105,46.805 v1@21.125,46.825
  Bottom Layer-L6 w0.165: v1(83.9,14.2) 84.455,13.645 J10.6@84.455,12.633
  Bottom Layer-L6 w0.2: U2.3@20.346,46.005 20.905,46.005 21.095,46.195 21.095,46.405 ; U2.2@20.346,46.405 21.095,46.405 ; v1@21.125,46.825 v1(21.175,46.825) 21.095,46.745 21.095,46.405
  Bottom Layer-L6 w0.3: D3.1@9.725,39.525 10.4,39.525 v1(10.425,39.5) ; D2.1@9.725,40.475 10.325,40.475 v1(10.45,40.35) ; v1(13.2,13.7) 13.95,14.45 C4.1@14.58,14.45 ; C30.1@16.5,48.4 v1(16.5,49.075) ; v1(56.3,35.325) 56.4,35.225 Q1.S@56.4,34.61
  Bottom Layer-L6 w0.4: v1(57.66,20.45) C10.1@57.66,21.3
  Bottom Layer-L6 w0.5: J3.6@4.626,28.028 5.672,28.028 v1(6.1,27.6) ; C28.1@11.128,5.715 11.138,5.725 v1(11.875,5.725) ; v1(13.3,47.85) 13.3,50.025 13.35,50.075 v1(13.425,50.075) ; v1(13.35,45.35) 14.09,45.35 C31.2@14.1,45.34 ; C29.1@13.4,49 v1@13.4,49.925 ; v1(17.893,43.028) C7.1@17.893,43.665 ; C3.1@18.1,17.6 18.1,16.8 v1(18.3,16.6) ; C5.1@19.084,34.626 19.797,35.339 19.797,35.4 C6.1@19.129,36.068 ; R20.1@19.619,23.622 20.522,23.622 v1(20.8,23.9) ; v1(20.845,43.028) C8.1@20.845,43.665 ; v1(20.9,15.3) R7.1@22,15.3 ; U1.2@22.08,18.3 22.7,18.3 v1(23.2,18.8) ; J7.13@24.328,6.794 v1(24.328,8) ; J7.10@28.078,6.794 v1(28.078,8) ; v1(31.8,9.1) 31.828,9.072 J7.7@31.828,6.794 ; J7.4@35.578,6.794 v1(35.578,8.2) ; v1(50.125,30.3) C17.1@51.1,30.3 ; C12.1@50.2,20.2 v1(51.5,20.2) ; v1(50.75,29.075) 51.1,28.725 C19.1@51.515,28.725 ; C18.1@51.54,27.225 51.54,27.94 v1(51.55,27.95) ; C11.2@52,22.44 v1(52.6,22.44) ; v1(52.7,20.3) 53.02,20.62 R38.1@53.02,21.3 ; C9.2@54.7,29.66 54.7,30.075 v1(55.075,30.45) ; J18.5@55.88,12.065 55.88,12.852 55.982,12.954 v1(57,12.954) ; R31.2@61.333,28.448 61.335,28.45 v1(62.075,28.45) ; R32.2@61.333,29.718 61.34,29.725 v1(62.05,29.725) ; R33.2@61.333,31.018 61.34,31.025 v1(62.05,31.025) ; R30.2@61.333,32.258 61.341,32.25 v1(62.075,32.25) ; SWD.3@73.279,54.229 73.3,54.25 v1(73.3,55.1) ; L14.1@82,1.85 83.35,1.85 83.9,2.4 v1(83.9,3.5) ; v1(83,52.4) C27.1@83.74,52.4
  Bottom Layer-L6 w0.61: v1(80.458,50.142) 81.042,50.142 C26.2@81.5,50.6 81.058,51.042 v1(80.458,51.042)
  other v1: 85,3.5 85.905,4.3 85.905,6 85.9,7.2 61.9,8.025 62.625,8.025 85.9,8.3 85.9,9.5 62.625,10.55 85.9,10.6 85.905,11.8 85.9,13.375 85.905,14.1 85,14.2 85.905,15.8 62.625,15.875 62.625,16.825 62.625,17.775 55.1,24.1 56.3,24.1 55.1,25.3 56.3,25.3 10.422,29.3 9.059,33.1 11.2,33.1 11.9,33.1 9.8,33.125 19.8,35.4
GPIO1_17: J1.78 J11.7 | length 107.5
  Top Layer-L1 w0.165: v1(40.513,9.6) J1.78@40.513,11.088
  Signal-L3 w0.121: 7.418,57.217 7.679,57.479 7.679,61.334 8.465,62.12 14.705,62.12 15.2,61.625 15.2,59.603 J11.7@16.51,58.293
  Signal-L3 w0.122: 7.418,57.217 5.237,55.036 5.237,27.619 8.609,24.247 12.467,24.247 14.447,22.267 14.447,17.679 15.447,16.679 15.447,6.035 19.448,2.034 35.323,2.034 40.513,7.224 v1(40.513,9.6)
GPIO1_18: J1.79 J11.11 | length 114.3
  Top Layer-L1 w0.165: v1(41.783,9.6) J1.79@41.783,11.088
  Signal-L3 w0.121: 5.383,55.534 7.431,57.583 7.431,61.437 8.362,62.368 19.597,62.368 20.325,61.64 20.325,59.558 J11.11@21.59,58.293
  Signal-L3 w0.122: 5.383,55.534 4.988,55.139 4.988,27.516 8.506,23.998 12.364,23.998 14.198,22.164 14.198,17.576 15.198,16.576 15.198,5.932 19.345,1.785 35.426,1.785 41.783,8.142 v1(41.783,9.6)
GPIO1_19: J1.76 J11.40 | length 73.1
  Top Layer-L1 w0.165: J1.76@37.973,11.088 v1(37.973,12.4) ; J11.40@57.15,60.833 58.6,59.383 58.6,54.1 v1(61.9,50.8)
  Signal-L3 w0.122: v1(37.973,12.4) 48.1,12.4 48.983,13.283 48.983,45.683 v1(50.1,46.8)
  Bottom Layer-L6 w0.165: v1(50.1,46.8) 51.9,46.8 55.1,50 57.7,50 58.4,49.3 61.1,49.3 61.9,50.1 v1(61.9,50.8)
GPIO1_20: J1.77 J11.13 | length 107.4
  Top Layer-L1 w0.165: J1.77@39.243,11.088 39.243,9.657 v1(39.9,9)
  Signal-L3 w0.121: 33.835,2.283 35.22,2.283 39.9,6.963 v1(39.9,9)
  Signal-L3 w0.122: v1(15,51.9) 13.713,53.187 10.169,53.187 9.565,53.791 7.329,53.791 6.013,52.475 6.013,28.487 10.004,24.496 12.57,24.496 14.696,22.37 14.696,17.782 15.696,16.782 15.696,6.138 19.551,2.283 33.835,2.283
  Bottom Layer-L6 w0.165: v1(15,51.9) 17.94,51.9 20.315,54.275 20.315,56.485 20.73,56.9 22.737,56.9 J11.13@24.13,58.293
GPIO1_28: J1.20 J11.15 | length 32.4
  Top Layer-L1 w0.165: J11.15@26.67,58.293 26.67,58.33 25.4,59.6 25.4,61.6 26.425,62.625 37.435,62.625 38.095,61.965 38.095,54.33 37.235,53.47 33.97,53.47 32.893,52.393 J1.20@32.893,50.888
GPIO1_29: J1.21 J11.16 | length 23.1
  Top Layer-L1 w0.165: J11.16@26.67,60.833 28.167,62.33 34.91,62.33 35.523,61.717 35.523,54.583 34.875,53.935 33.235,53.935 31.623,52.323 J1.21@31.623,50.888
GPIO1_30: J1.22 J11.18 | length 13.8
  Top Layer-L1 w0.165: J11.18@29.21,60.833 30.468,59.575 32.47,59.575 33,59.045 33,54.61 30.353,51.963 J1.22@30.353,50.888
GPIO3_15: J1.25 J11.22 | length 21.1
  Top Layer-L1 w0.165: J1.25@26.543,50.888 v1(26.543,52.757)
  Signal-L3 w0.122: v1(26.543,52.757) 26.543,53.102 25.39,54.255 25.39,61.725 25.985,62.32 32.803,62.32 J11.22@34.29,60.833
GPIO4_20: J1.2 J11.26 | length 27.5
  Top Layer-L1 w0.165: J11.26@38.93,60.648 J11.26@38.93,61.43
  Top Layer-L1 w0.191: J11.26@38.93,61.43 38.969,61.391 39.928,61.391 40.837,62.3 52.5,62.3 53.34,61.46 53.34,54.66 55.753,52.247 J1.2@55.753,50.888
GPIO4_21: J1.3 J11.29 | length 17.8
  Top Layer-L1 w0.191: J11.29@44.45,58.293 45.727,59.57 47.63,59.57 48.235,58.965 48.235,54.065 48.6,53.7 53,53.7 54.483,52.217 J1.3@54.483,50.888
GPIO4_22: J1.4 J11.31 | length 14.3
  Top Layer-L1 w0.191: J11.31@46.99,58.293 45.7,57.003 45.7,54.3 46.9,53.1 52.5,53.1 53.213,52.387 J1.4@53.213,50.888
GPIO5_03: J1.102 J11.32 | length 49.2
  Top Layer-L1 w0.165: J11.32@46.99,60.833 48.223,59.6 50.4,59.6 50.8,59.2 v1(50.8,54.3) ; v1(58.95,27.2) 60.351,27.2 J1.102@60.373,27.178
  Signal-L3 w0.121: v1(58.95,27.2) 58.262,27.2 57.136,28.326 57.136,30.836 57.883,31.582 57.883,34.73 58.344,35.192 58.344,51.044 59.5,52.2 v1(59.5,54.3)
  Bottom Layer-L6 w0.165: v1(50.8,54.3) 51.319,53.781 58.981,53.781 v1(59.5,54.3)
I2C2_SCL: J1.23 J11.5 | length 26.5
  Top Layer-L1 w0.165: v1(13.475,51.925) 13.525,51.925 14.499,52.899 15.379,52.899 15.719,53.239 22.14,53.239 22.482,53.582 27.825,53.582 29.083,52.324 J1.23@29.083,50.888
  Bottom Layer-L6 w0.165: v1(13.475,51.925) 13.01,52.39 13.01,52.903 13.853,53.745 14.315,53.745 15.195,54.625 15.195,57.068 J11.5@13.97,58.293
I2C2_SDA: J1.24 J11.3 | length 26.5
  Top Layer-L1 w0.165: v1(13,50.95) 13.242,50.95 14.899,52.607 15.5,52.607 15.818,52.925 22.239,52.925 22.603,53.29 26.703,53.29 27.813,52.179 J1.24@27.813,50.888
  Bottom Layer-L6 w0.165: J11.3@11.43,58.293 11.43,57.55 10.22,56.34 10.22,53.975 13,51.195 v1(13,50.95)
I2C3_SCL: J1.89 J11.28 | length 69.8
  Top Layer-L1 w0.165: J1.89@54.483,11.088 54.5,11.071 v1(54.5,9.6)
  Signal-L3 w0.121: J11.28@41.91,60.833 42.237,60.833 43.475,59.595 52.48,59.595 53.385,58.69 53.385,57.45 53.91,56.925 55.095,56.925 55.91,56.11 55.91,53.51 55.584,53.185 55.584,35.029 55.816,34.797 55.816,32.635 55.684,32.503 55.684,30.854 55.791,30.747 55.791,28.954 55.394,28.556 55.394,26.917 56.767,25.543 56.767,23.361 56.064,22.658 56.064,21.241 55.784,20.961 55.784,13.508 57.1,12.193 57.1,9.4 56.833,9.133 54.967,9.133 v1(54.5,9.6)
I2C3_SDA: J1.88 J11.27 | length 56.9
  Top Layer-L1 w0.165: v1(52.555,15.065) 52.555,13.07 53.213,12.412 J1.88@53.213,11.088
  Signal-L3 w0.121: J11.27@41.91,58.293 43.18,57.023 43.18,54.945 43.925,54.2 49.381,54.2 53.066,50.515 53.066,31.045 52.901,30.88 52.901,29.166 52.885,29.15 52.885,26.942 54.135,25.692 54.135,18.492 54.601,18.026 54.601,17.11 v1(52.555,15.065)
